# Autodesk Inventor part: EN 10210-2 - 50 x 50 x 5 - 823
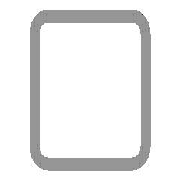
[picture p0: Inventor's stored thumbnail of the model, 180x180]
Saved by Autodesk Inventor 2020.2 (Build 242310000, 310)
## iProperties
Created: 2019-01
Part Number: EN 10210-2 - 50 x 50 x 5 - 823
Material: Stahl, weich
Description: Rohrleitung
Document SubType Name: Modeling
Standard: DIN
Designer: lutzd
Standard Revision: 2006-07
Standards Organization: DIN
Language: de-DE
Size Designation: 50 x 50 x 5
Categories: <MemberInstance><Categories><Category DisplayName="Profile" InternalName="089c4875-fa83-4c05-b084-43b9cc11f5ed" Mnemonic="GRDR"><CategoryParameter DisplayName="
Stock Number: 50 x 50 x 5
Mass: 5641.19 g
Surface Area: 2803.65 cm^2
Volume: 718.623 cm^3
Density: 7.85 g/cm^3
Appearance: Semi-Polished(8)
IsCustomPart: 1
_CCFamilyMember: 16
_CCFamilyDisplayName: DIN EN 10210-2 (USAS B17.1 quadratisch) - Rohrleitung — In Klammern angegebene Größen wurden aufgehoben
_FrameMemberDoc: Frame Member File
_Version: 15.0.0
_GetPNFromCC: 1
G_L: 823,000 mm
G_W: 50,000 mm
G_H: 50,000 mm
DocNumber: ADSK-014264
Folder: .
Dimensions: 50x50x823 mm
Mass: 5,641 kg
+0CEAC6CA-D675-4251-9FD5-41A5D1FB52B2+SCHNITTDETAIL1: Schnittwinkel 90,00 grd
+634FB6A4-B620-422F-8C31-5EEF032E0E47+SCHNITTDETAIL2: Schnittwinkel 90,00 grd
VLT_Material: Stahl, weich
Title: Profil-Bauteil
Author: lutzd
Revision Number: -
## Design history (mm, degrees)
node "Startebene"
node "Endebene"
sketch "Skizze"
  geometry: L1 (-25, -17.5)-(-25, 17.5); L2 (-17.5, 25)-(17.5, 25); L3 (25, 17.5)-(25, -17.5); L4 (17.5, -25)-(-17.5, -25); L5 (-15, 20)-(15, 20); L6 (20, 15)-(20, -15); L7 (15, -20)-(-15, -20); L8 (-20, -15)-(-20, 15); L9 (0, 37.175)-(0, -37.175) reference; L10 (-37.175, 0)-(37.175, 0) reference; A1 r 7.5 centre (-17.5, -17.5) between (-25, -17.5) and (-17.5, -25); A2 r 7.5 centre (-17.5, 17.5) between (-17.5, 25) and (-25, 17.5); A3 r 7.5 centre (17.5, 17.5) between (25, 17.5) and (17.5, 25); A4 r 7.5 centre (17.5, -17.5) between (17.5, -25) and (25, -17.5); A5 r 5 centre (-15, -15) between (-20, -15) and (-15, -20); A6 r 5 centre (-15, 15) between (-15, 20) and (-20, 15); A7 r 5 centre (15, 15) between (20, 15) and (15, 20); A8 r 5 centre (15, -15) between (15, -20) and (20, -15)
  constraints: 16 end point, 16 point on circle, 16 tangent, 8 centre point, 6 equal radius, 4 parallel, 2 perpendicular, 2 other
  dimensions: "d7" = 7.5 radius of A1 (= G_IR); "d10" = 50 distance between parallel lines of L2 L4 (= G_H); "d11" = 50 distance between parallel lines of L1 L3 (= G_W); "d12" = 5 distance between parallel lines of L3 L6 (= G_T); "d15" = 25 distance between parallel lines of L2 L10 (= 0.5 x d10); "d16" = 25 distance between parallel lines of L9 L3 (= 0.5 x d11); "d19" = 5 radius of A5 (= G_T); "d20" = 5 distance between parallel lines of L4 L7 (= G_T)
extrude "Körper" new body sketch "Skizze" stored distance "d3" = 823 (= G_L); taper "d4" = 0 deg
node "Driven Length"
  sketch "Sketch3"
    geometry: L1 (0, 0)-(10, 0) reference
    constraints: 2 end point, 1 horizontal
  workplane "Work Plane3"
  sketch "Sketch4"
    geometry: L1 (-2, 50)-(12, 50) reference; L2 (-2, 873)-(12, 873) reference
    dimensions: "d18" = 823 distance between parallel lines of L1 L2 (derived)
workplane "Arbeitsebene4"
feature "Trennen1"
workplane "Arbeitsebene5"
feature "Trennen2"
body "Solid1"
other parameters: "G_W" = 50 [user parameter; used in 1 equation term], "G_H" = 50 [user parameter; used in 1 equation term], "G_T" = 5 [user parameter; used in 3 equation terms], "G_IR" = 7.5 [user parameter; used in 1 equation term], "G_L" = 823 (= d18) [user parameter; used in 1 equation term], "G_OFFSET_END" = -35 [user parameter; used in 1 equation term], "d14" = 873 (= G_OFFSET_END + B_L), "B_L" = 908 [user parameter; used in 1 equation term], "d17" = 90 deg
